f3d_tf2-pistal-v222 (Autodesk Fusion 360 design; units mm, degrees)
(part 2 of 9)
sketch "Sketch12" plane through (15, 0, 0) normal (-1, 0, 0) x axis (0, -1, 0)
  line L1 (-233.7172, -58) -> (-233.7172, -15.2961)
  line L2 (-211.3329, -58) -> (-233.7172, -58)
  line L3 (-182.3761, -29.6952) -> (-211.3329, -58)
  line L4 (-196.2783, -29.6952) -> (-182.3761, -29.6952)
  line L5 (-196.2783, -15.2961) -> (-196.2783, -29.6952)
  line L6 (-233.7172, -15.2961) -> (-196.2783, -15.2961)
  line L7 (-233.7172, -58) -> (-211.3329, -58)
  line L8 (-233.7172, -79.8803) -> (-233.7172, -58)
  line L9 (-211.3329, -58) -> (-233.7172, -79.8803)
  line L10 (-227, -25.812) -> (-233.7172, -25.812)
  line L11 (-221, -47) -> (-227, -25.812)
  line L12 (-216.582, -57.5943) -> (-223.3416, -55.7758)
  line L13 (-223.3416, -55.7758) -> (-242.8252, -128.2009)
  line L14 (-220.8968, -47.3272) -> (-223.3416, -55.7758)
  line L15 (-221, -47) -> (-220.8968, -47.3272)
  point P11 (-233.7172, -25.812)
  point P14 (-223.3416, -55.7758)
  point P17 (-223.3416, -55.7758)
  coincident L1 P11
  perpendicular L1 L10
  coincident P14 P17
extrude "Extrude8" new body sketch "Sketch12" profile of L1 L2 L7 L8 L9 L10 L11 L13 L14 L15 along normal blind 15
delete_face "DeleteFace5"
sketch "Sketch13" plane through (17.9981, 0, 0) normal (1, 0, 0) x axis (0, 1, 0)
  line L1 (149.9264, -64.082) -> (155.6873, -48.7302)
  line L2 (132.0175, -155.1313) -> (149.9264, -64.082)
  line L3 (171.9916, -32.8813) -> (200.2987, -133.9094)
  curve K1 (162.1012, -64.9669) -> (152.9897, -33.2509)
  line L4 (134.4899, -205.3434) -> (162.1012, -64.9669)
  line L5 (149.9264, -64.082) -> (132.0175, -155.1313)
  arc A1 centre (162.3398, -25.3102) radius 133.3153 clockwise from (186.1858, -156.4755) to (132.0175, -155.1313)
  arc A2 centre (182.9662, -138.7658) radius 18 clockwise from (200.2987, -133.9094) to (186.1858, -156.4755)
  arc A3 centre (162.3398, -25.3102) radius 12.267 clockwise from (152.9897, -33.2509) to (171.9916, -32.8813)
  arc A4 centre (141.1755, -43.2845) radius 15.5 clockwise from (152.9897, -33.2509) to (155.6873, -48.7302)
  point P10 (152.9897, -33.2509)
  point P12 (152.9897, -33.2509)
  coincident P10 P12
  parallel L4 L5
split "Split6"
split "Split7"
move "Move13"
combine "Combine6"
delete_face "DeleteFace6"
delete_face "DeleteFace7"
delete_face "DeleteFace8"
delete_face "DeleteFace9"
delete_face "DeleteFace10"
delete_face "DeleteFace11"
delete_face "DeleteFace12"
delete_face "DeleteFace13"
delete_face "DeleteFace14"
delete_face "DeleteFace15"
fillet "Fillet12" radius 1
fillet "Fillet13" radius 1
sketch "Sketch14" plane through (12.4927, 0, 0) normal (1, 0, 0) x axis (0, 1, 0)
  line L1 (199.7352, -62.1263) -> (223.3416, -55.7758)
  line L2 (199.7359, -62.129) -> (199.7352, -62.1263)
  line L3 (199.7459, -62.1263) -> (199.7359, -62.129)
  line L4 (219.2287, -134.5488) -> (199.7459, -62.1263)
  line L5 (242.8252, -128.2009) -> (219.2287, -134.5488)
  line L6 (223.3416, -55.7758) -> (242.8252, -128.2009)
  line L7 (233.7172, -79.8803) -> (211.3329, -58)
  line L8 (233.7172, -15.2961) -> (233.7172, -79.8803)
  curve K1 (274.1373, -137.1288) -> (233.7172, -54.0384)
  line L9 (250.6342, -126.1002) -> (242.8252, -128.2009)
  line L10 (255.2867, -143.3949) -> (250.6342, -126.1002)
  line L11 (274.1373, -137.1288) -> (255.2867, -143.3949)
  point P12 (233.7172, -54.0384)
  point P7 (242.8252, -128.2009)
  point P15 (242.8252, -128.2009)
  coincident L8 P12
  coincident P7 P15
  perpendicular L6 L9
  perpendicular L9 L10
extrude "Extrude9" new body sketch "Sketch14" profile of L6 L7 L8 K1 L9 L10 L11 along normal blind 7.505 and against normal blind 12.493
split "Split8"
split "Split9"
combine "Combine7"
move_face "MoveFace4"
extrude "Extrude10" cut of existing geometry blind -1
fillet "Fillet14" radius 10
sketch "Sketch15" plane through (-18.0019, 0, 0) normal (-1, 0, 0) x axis (0, -1, 0)
  curve K1 (-163.8476, -56.0881) -> (-163.931, -57.8793)
  curve K2 (-163.8476, -56.0881) -> (-150.2901, -27.6086)
  line L1 (-200.2987, -133.9094) -> (-171.9916, -32.8813)
  line L2 (-163.0153, -60.3193) -> (-143.9303, -157.3483)
  line L3 (-163.931, -57.8793) -> (-163.0153, -60.3193)
  curve K3 (-150.2901, -27.6086) -> (-148.0856, -25.9147)
  arc A1 centre (-162.3398, -25.3102) radius 12.267 clockwise from (-171.9916, -32.8813) to (-150.2901, -27.6086)
  arc A2 centre (-182.9662, -138.7658) radius 18 clockwise from (-186.1858, -156.4755) to (-200.2987, -133.9094)
  arc A3 centre (-162.3398, -25.3102) radius 133.3153 clockwise from (-143.9303, -157.3483) to (-186.1858, -156.4755)
  arc A4 centre (-162.3398, -25.3102) radius 14.267 clockwise from (-170.265, -13.447) to (-148.0856, -25.9147)
  circle C1 centre (-162.3398, -25.3102) radius 14.267
  point P12 (-148.0856, -25.9147)
  concentric A4 C1
  coincident P12 C1
extrude "Extrude11" new body sketch "Sketch15" profile of K2 C1 K3 against normal blind 5
combine "Combine8"
fillet "Fillet15" radius 2
sketch "Sketch16" plane through (17.9981, 0, 0) normal (1, 0, 0) x axis (0, 1, 0)
  curve K1 (163.8476, -56.0881) -> (163.931, -57.8793)
  line L1 (163.0153, -60.3193) -> (163.931, -57.8793)
  line L2 (143.9303, -157.3483) -> (163.0153, -60.3193)
  line L3 (171.9916, -32.8813) -> (200.2987, -133.9094)
  curve K2 (150.2901, -27.6086) -> (163.8476, -56.0881)
  curve K3 (148.0856, -25.9147) -> (150.2901, -27.6086)
  arc A1 centre (162.3398, -25.3102) radius 133.3153 clockwise from (186.1858, -156.4755) to (143.9303, -157.3483)
  arc A2 centre (182.9662, -138.7658) radius 18 clockwise from (200.2987, -133.9094) to (186.1858, -156.4755)
  arc A3 centre (162.3398, -25.3102) radius 12.267 clockwise from (150.2901, -27.6086) to (171.9916, -32.8813)
  arc A4 centre (162.3398, -25.3102) radius 14.267 clockwise from (148.0856, -25.9147) to (170.265, -13.447)
  circle C1 centre (162.3398, -25.3102) radius 14.267
  point P13 (148.0856, -25.9147)
  concentric A1 C1
  coincident P13 C1
extrude "Extrude12" new body sketch "Sketch16" profile of K2 C1 K3 against normal blind 5
combine "Combine9"
fillet "Fillet16" radius 2
combine "Combine10"
move_face "MoveFace5"
combine "Combine11"
move_face "MoveFace6"
move_face "MoveFace7"
move "Move1"
move_face "MoveFace1"
move "Move14" RotateAngle 30
sketch "Sketch17" plane through (0, 26.7264, -99.3486) normal (0, -0.2598, 0.9657) x axis (1, 0, 0)
  line L1 (5.4981, 153.3307) -> (-5.5019, 153.3307)
  line L2 (12.4981, 176.7509) -> (12.4981, 160.3307)
  line L3 (9.3981, 176.7509) -> (12.4981, 176.7509)
  line L4 (9.3981, 163.0135) -> (9.3981, 176.7509)
  line L5 (8.9981, 162.6135) -> (9.3981, 163.0135)
  line L6 (8.9981, 160.2587) -> (8.9981, 162.6135)
  line L7 (-4.5019, 155.7587) -> (4.4981, 155.7587)
  line L8 (-9.0019, 162.6135) -> (-9.0019, 160.2587)
  line L9 (-9.4019, 163.0135) -> (-9.0019, 162.6135)
  line L10 (-9.4019, 176.7509) -> (-9.4019, 163.0135)
  line L11 (-12.4949, 176.7509) -> (-9.4019, 176.7509)
  line L12 (-12.4949, 176.7407) -> (-12.4949, 176.7509)
  line L13 (-12.5019, 176.7407) -> (-12.4949, 176.7407)
  line L14 (-12.5019, 160.3307) -> (-12.5019, 176.7407)
  line L15 (-13.0019, 160.1268) -> (-13.0019, 159.1143)
  line L16 (12.9981, 159.1143) -> (12.9981, 160.1268)
  line L17 (12.9981, 160.1268) -> (-13.0019, 160.1268)
  arc A1 centre (-5.5019, 160.3307) radius 7 clockwise from (-5.5019, 153.3307) to (-12.5019, 160.3307)
  arc A2 centre (5.4981, 160.3307) radius 7 clockwise from (12.4981, 160.3307) to (5.4981, 153.3307)
  arc A3 centre (4.4981, 160.2587) radius 4.5 clockwise from (8.9981, 160.2587) to (4.4981, 155.7587)
  arc A4 centre (-4.5019, 160.2587) radius 4.5 clockwise from (-4.5019, 155.7587) to (-9.0019, 160.2587)
  arc A5 centre (-0.0019, 162.4117) radius 13.4117 clockwise from (12.9981, 159.1143) to (-13.0019, 159.1143)
  point P25 (-13.0019, 160.1268)
  point P28 (-13.0019, 160.1268)
  point P26 (12.9981, 160.1268)
  point P29 (12.9981, 160.1268)
  point P27 (12.9981, 159.1143)
  point P31 (12.9981, 159.1143)
  point P24 (-13.0019, 159.1143)
  point P30 (-13.0019, 159.1143)
  coincident P25 P28
  coincident P26 P29
  coincident P27 P31
  coincident P24 P30
split "Split10"
delete_face "DeleteFace16"
delete_face "DeleteFace17"
delete_face "DeleteFace18"
fillet "Fillet17" radius 1.5
sketch "Sketch18" plane through (12.4927, 0, 0) normal (1, 0, 0) x axis (0, 1, 0)
  line L1 (242.8252, -128.2009) -> (228.4379, -74.7198)
  line L2 (250.6342, -126.1002) -> (242.8252, -128.2009)
  line L3 (255.2867, -143.3949) -> (250.6342, -126.1002)
  line L4 (274.1373, -137.1288) -> (255.2867, -143.3949)
  curve K1 (261.4021, -106.9418) -> (274.1373, -137.1288)
  line L5 (228.4379, -74.7198) -> (261.4021, -106.9418)
  arc A1 centre (236.9306, -113.2524) radius 18 clockwise from (249.5127, -100.3804) to (248.5737, -126.9797)
  arc A2 centre (236.9306, -113.2524) radius 21.6199 clockwise from (252.2054, -97.9522) to (250.3613, -130.1945)
  point P13 (252.2054, -97.9522)
  point P10 (236.9306, -113.2524)
  point P11 (236.9306, -113.2524)
  coincident L5 P13
  coincident P10 P11
extrude "Extrude13" add sketch "Sketch18" profile of L3 L4 K1 L5 A2 along normal blind 7.505
delete_face "DeleteFace19"
move_face "MoveFace8"
sketch "Sketch19" plane through (19.9977, 0, 0) normal (1, 0, 0) x axis (0, 1, 0)
  curve K1 (274.1373, -137.1288) -> (234.5414, -55.1914)
  curve K2 (232.7172, -49.4332) -> (234.5414, -55.1914)
  line L1 (232.7172, -29.6952) -> (232.7172, -49.4332)
  line L2 (196.2783, -29.6952) -> (232.7172, -29.6952)
  line L3 (182.3761, -29.6952) -> (196.2783, -29.6952)
  line L4 (252.2054, -97.9522) -> (182.3761, -29.6952)
  line L5 (245.7812, -146.5546) -> (242.446, -134.1569)
  line L6 (274.1373, -137.1288) -> (245.7812, -146.5546)
  line L7 (250.9952, -129.672) -> (249.8674, -128.5049)
  line L8 (238.5226, -140.3558) -> (250.9952, -129.672)
  arc A1 centre (236.9306, -113.2524) radius 21.6199 clockwise from (252.2054, -97.9522) to (242.446, -134.1569)
  arc A2 centre (162.3398, -25.3102) radius 135.3153 clockwise from (249.8674, -128.5049) to (217.1145, -149.0436)
  point P13 (249.8674, -128.5049)
  point P15 (249.8674, -128.5049)
  point P16 (250.9952, -129.672)
  coincident P13 P15
  coincident A1 P16
  tangent A1 L8
extrude "Extrude14" cut sketch "Sketch19" profile of A1 L5 A2 L8 against normal blind 0.5
move_face "MoveFace9"
move_face "MoveFace10"
mirror "Mirror3" mirrorStitchTolerance 0.1
sketch "Sketch20" plane through (21.9981, 0, 0) normal (1, 0, 0) x axis (0, 1, 0)
  line L1 (232.7172, -15.2961) -> (232.7172, -29.6952)
  line L2 (144.3129, -15.2961) -> (232.7172, -15.2961)
  line L3 (144.3129, -29.6952) -> (144.3129, -15.2961)
  line L4 (232.7172, -29.6952) -> (144.3129, -29.6952)
  line L5 (237.721, -10) -> (210, -10)
  line L6 (237.721, -33.2426) -> (237.721, -10)
  line L7 (210, -33.2426) -> (237.721, -33.2426)
  line L8 (210, -10) -> (210, -33.2426)
  horizontal L5
  vertical L6
  horizontal L7
  vertical L8
extrude "Extrude15" new body sketch "Sketch20" profile of L1 L2 L4 L5 L6 L7 L8 against normal blind 2
mirror "Mirror4" mirrorStitchTolerance 0.1
combine "Combine12"
combine "Combine13"
sketch "Sketch21" plane through (0, 0, -25.812) normal (0, 0, 1) x axis (-1, 0, 0)
  line L1 (-15, -232.7172) -> (-15, -227)
  line L2 (0, -232.7172) -> (-15, -232.7172)
  line L3 (0, -227) -> (0, -232.7172)
  line L4 (-15, -227) -> (0, -227)
  line L5 (-8.7952, -248.3191) -> (-8.7952, -208.8666)
  line L6 (8.7048, -248.3191) -> (8.7048, -208.8666)
extrude "Extrude16" add sketch "Sketch21" profile of L1 L2 L4 L5 along normal blind 10.516
sketch "Sketch22" plane through (0, 0, -25.812) normal (0, 0, 1) x axis (-1, 0, 0)
  line L1 (15, -227) -> (15, -232.7172)
  line L2 (0, -227) -> (15, -227)
  line L3 (0, -232.7172) -> (0, -227)
  line L4 (15, -232.7172) -> (0, -232.7172)
  line L5 (8.7048, -248.3191) -> (8.7048, -208.8666)
extrude "Extrude17" add sketch "Sketch22" profile of L1 L2 L4 L5 along normal blind 10.516
move_face "MoveFace11"
move_face "MoveFace12"
extrude "Extrude18" add of existing geometry blind 0
extrude "Extrude19" add of existing geometry blind 0
fillet "Fillet18" radius 8
extrude "Extrude20" cut of existing geometry blind 0
move_face "MoveFace13"
fillet "Fillet19" radius 8
delete_face "DeleteFace20"
move_face "MoveFace14"
delete_face "DeleteFace21"
delete_face "DeleteFace22"
move_face "MoveFace15"
fillet "Fillet20" radius 10
fillet "Fillet21" radius 10
fillet "Fillet22" radius 1
mirror "Mirror5" mirrorStitchTolerance 0.1 bodies "Gear 2"
combine "Combine14"
sketch "Sketch23" plane through (19.9977, 0, 0) normal (1, 0, 0) x axis (0, 1, 0)
  line L1 (240.0468, -84.669) -> (183.8067, -29.6952)
  curve K1 (240.0468, -84.669) -> (225.9553, -60.3717)
  curve K2 (225.9553, -60.3717) -> (222.2172, -48.7291)
  line L2 (222.2172, -15.2961) -> (222.2172, -48.7291)
  line L3 (210, -15.2961) -> (222.2172, -15.2961)
  line L4 (210, -29.6952) -> (210, -15.2961)
  line L5 (196.2783, -29.6952) -> (210, -29.6952)
  line L6 (183.8067, -29.6952) -> (196.2783, -29.6952)
  line L7 (252.4034, -17.2714) -> (230.0662, -37.4329)
  line L8 (252.4034, -15.2961) -> (252.4034, -17.2714)
  line L9 (222.2172, -15.2961) -> (252.4034, -15.2961)
  line L10 (230.0662, -37.4329) -> (222.2172, -37.5779)
  line L11 (222.2172, -37.5779) -> (222.2172, -15.2961)
  point P6 (222.2172, -15.2961)
  point P13 (222.2172, -15.2961)
  point P14 (222.2172, -37.5779)
  point P15 (222.2172, -15.2961)
  perpendicular L3 L8
  coincident P6 P13
  perpendicular L2 L9
  coincident L2 P14
  coincident P6 P15
extrude "Extrude21" new body sketch "Sketch23" profile of L2 L7 L8 L9 L10 L11 against normal blind 39.995
fillet "Fillet23" radius 19.5
chamfer "Chamfer1" distance 10
chamfer "Chamfer2" distance 10
chamfer "Chamfer3" distance 7
split "Split11"
move_face "MoveFace16"
combine "Combine15"
split "Split12"
split "Split13"
combine "Combine16"
move_face "MoveFace1"
fillet "Fillet24" radius 2
sketch "Sketch24" plane through (-19.9977, 0, 0) normal (-1, 0, 0) x axis (0, -1, 0)
  line L1 (-196.2783, -29.6952) -> (-183.8067, -29.6952)
  line L2 (-210, -29.6952) -> (-196.2783, -29.6952)
  line L3 (-210, -15.2961) -> (-210, -29.6952)
  line L4 (-222.2172, -15.2961) -> (-210, -15.2961)
  line L5 (-222.2172, -48.7291) -> (-222.2172, -15.2961)
  curve K1 (-222.2172, -48.7291) -> (-225.9553, -60.3717)
  curve K2 (-225.9553, -60.3717) -> (-240.0468, -84.669)
  line L6 (-196.2783, -29.6952) -> (-210, -29.6952)
  line L7 (-144.3129, -29.6952) -> (-196.2783, -29.6952)
  line L8 (-264.6265, -140.2903) -> (-247.6, -145.9501)
  line L9 (-256.1132, -143.1202) -> (-210, -29.6952)
  curve K3 (-257.3894, -122.901) -> (-264.6265, -140.2903)
  line L10 (-247.6, -145.9501) -> (-264.6265, -140.2903)
  line L11 (-244.9647, -136.1543) -> (-247.6, -145.9501)
  line L12 (-244.9647, -136.1543) -> (-244.6769, -135.0842)
  line L13 (-250.9952, -129.672) -> (-244.6769, -135.0842)
  line L14 (-251.6458, -130.4315) -> (-250.9952, -129.672)
  line L15 (-182.3761, -29.6952) -> (-183.8067, -29.6952)
  line L16 (-239.3478, -85.3841) -> (-240.0468, -84.669)
  line L17 (-182.3761, -29.6952) -> (-239.3478, -85.3841)
  arc A1 centre (-236.9306, -113.2524) radius 22.6199 clockwise from (-251.6458, -130.4315) to (-257.3894, -122.901)
  point P10 (-210, -29.6952)
  point P16 (-210, -29.6952)
  point P17 (-256.1132, -143.1202)
  coincident P10 P16
  midpoint L8 P17
extrude "Extrude22" new body sketch "Sketch24" profile of L1 L2 L6 L7 L8 L9 L10 L11 L12 L13 L15 L17 against normal blind 1.996
mirror "Mirror6" mirrorStitchTolerance 0.1
combine "Combine17"
combine "Combine18"
chamfer "Chamfer4" distance 0.34
sketch "Sketch25" plane through (0, 0, -29.6952) normal (0, 0, 1) x axis (-1, 0, 0)
  line L1 (-18.0017, -196.2783) -> (-18.0017, -182.3761)
  line L2 (-15, -196.2783) -> (-18.0017, -196.2783)
  line L3 (-15, -182.3761) -> (-15, -196.2783)
  line L4 (-18.0017, -182.3761) -> (-15, -182.3761)
  line L5 (-20, -182.3761) -> (-18.0017, -182.3761)
  line L6 (-19.9981, -196.2783) -> (-18.0017, -196.2783)
  line L7 (-19.9981, -144.3129) -> (-19.9981, -196.2783)
  point P2 (-18.0017, -182.3761)
  point P6 (-18.0017, -182.3761)
  coincident P2 P6
  perpendicular L1 L5
extrude "Extrude23" new body sketch "Sketch25" along normal blind 2
mirror "Mirror7" mirrorStitchTolerance 0.1
combine "Combine19"
combine "Combine20"
move_face "MoveFace17"
split "Split14"
combine "Combine21"
combine "Combine22"
move_face "MoveFace18"
sketch "Sketch26" plane through (19.9977, 0, 0) normal (1, 0, 0) x axis (0, 1, 0)
  line L1 (227.5887, -72.0555) -> (210, -28.7924)
  curve K1 (227.5887, -72.0555) -> (227.8766, -72.7728)
  line L2 (240.0468, -84.669) -> (227.8766, -72.7728)
  curve K2 (240.0468, -84.669) -> (225.9553, -60.3717)
  curve K3 (225.9553, -60.3717) -> (222.2172, -48.7291)
  line L3 (222.2172, -18.0746) -> (222.2172, -48.7291)
  line L4 (225.4047, -18.0157) -> (222.2172, -18.0746)
  curve K4 (225.4047, -18.0157) -> (225.4041, -17.9302)
  line L5 (225.4041, -17.9302) -> (225.4039, -17.9036)
  curve K5 (225.4039, -17.9036) -> (225.4034, -17.7015)
  line L6 (225.4034, -0.2961) -> (225.4034, -17.7015)
  line L7 (210, -0.2961) -> (225.4034, -0.2961)
  line L8 (210, -28.7924) -> (210, -0.2961)
  line L9 (263.0459, -29.0909) -> (215, 35)
split "Split15"
remove_body "RemoveBody1"
remove_body "RemoveBody2"
sketch "Sketch27" plane through (0, 0, -0.2961) normal (0, 0, 1) x axis (-1, 0, 0)
  line L1 (-9.0952, -241.4598) -> (-16.2464, -241.4598)
  line L2 (-9.0952, -227) -> (-9.0952, -241.4598)
  line L3 (-15, -227) -> (-9.0952, -227)
  line L4 (-15, -196.2783) -> (-15, -227)
  line L5 (-19.9981, -196.2783) -> (-15, -196.2783)
  line L6 (-19.9981, -144.3129) -> (-19.9981, -196.2783)
  line L7 (-21.9981, -144.3129) -> (-19.9981, -144.3129)
  line L8 (-21.9981, -210) -> (-21.9981, -144.3129)
  line L9 (-19.9977, -210) -> (-21.9981, -210)
  line L10 (-19.9977, -225.4034) -> (-19.9977, -210)
  line L11 (-17.3189, -238.8705) -> (-19.9977, -225.4034)
  line L12 (-16.2464, -241.4598) -> (-17.3189, -238.8705)
  curve K1 (-21.9981, -210) -> (-19.9977, -222.2172)
  point P14 (-19.9977, -222.2172)
  point P15 (-19.9977, -222.2172)
  point P10 (-21.9981, -210)
  point P17 (-21.9981, -210)
  coincident P14 P15
  coincident P10 P17
extrude "Extrude24" new body sketch "Sketch27" profile of L9 L10 K1 against normal blind 29.399
move_face "MoveFace19"
move_face "MoveFace20"
move_face "MoveFace21"
delete_face "DeleteFace23"
move_face "MoveFace22"
delete_face "DeleteFace24"
sketch "Sketch28" plane through (0, 144.3129, 0) normal (0, -1, 0) x axis (1, 0, 0)
  line L1 (-18.3981, -0.2961) -> (-18.3981, -29.6952)
  line L2 (-19.9977, -0.2961) -> (-18.3981, -0.2961)
  line L3 (-19.9977, -29.6952) -> (-19.9977, -0.2961)
  line L4 (-18.3981, -29.6952) -> (-19.9977, -29.6952)
  line L5 (-12.7981, -21.7117) -> (-12.7981, -21.8255)
  line L6 (-12.7981, -21.9467) -> (-12.7981, -21.8116)
  line L7 (-12.7981, -21.9467) -> (-12.7981, -22.2857)
  line L8 (-12.7981, -22.2857) -> (-12.7981, -21.8768)
  line L9 (-12.7981, -21.8768) -> (-12.7981, -20.9044)
  line L10 (-12.7981, -20.8065) -> (-12.7981, -20.9044)
  line L11 (-12.7981, -20.2907) -> (-12.7981, -20.8065)
  line L12 (-12.7981, -20.2907) -> (-12.7981, -20.2008)
  line L13 (-12.7981, -19.9583) -> (-12.7981, -20.2008)
  line L14 (-12.7981, -20.0459) -> (-12.7981, -19.9798)
  line L15 (-12.7981, -20.0799) -> (-12.7981, -19.9159)
  line L16 (-12.7981, -19.9159) -> (-12.7981, -19.4286)
  line L17 (-12.7981, -19.4286) -> (-12.7981, -18.8037)
  line L18 (-12.7981, -18.7819) -> (-12.7981, -18.8037)
  line L19 (-12.7981, -18.3715) -> (-12.7981, -18.7819)
  line L20 (-12.7981, -18.3715) -> (-12.7981, -18.2733)
  line L21 (-12.7981, -17.879) -> (-12.7981, -18.2733)
  line L22 (-12.7981, -17.866) -> (-12.7981, -17.879)
  line L23 (-12.7981, -17.866) -> (-12.7981, -17.2868)
  line L24 (-12.7981, -17.2868) -> (-12.7981, -16.7952)
  line L25 (-12.7981, -16.7952) -> (-12.7981, -16.5906)
  line L26 (-12.7981, -16.6706) -> (-12.7981, -16.6129)
  line L27 (-12.7981, -16.4281) -> (-12.7981, -16.6868)
  line L28 (-12.7981, -16.4281) -> (-12.7981, -16.3366)
  line L29 (-12.7981, -15.8288) -> (-12.7981, -16.3366)
  line L30 (-12.7981, -15.7388) -> (-12.7981, -15.8288)
  line L31 (-12.7981, -15.7388) -> (-12.7981, -14.7985)
  line L32 (-12.7981, -14.7985) -> (-12.7981, -14.3775)
  line L33 (-12.7981, -14.3775) -> (-12.7981, -14.6657)
  line L34 (-12.7981, -14.794) -> (-12.7981, -14.6657)
  line L35 (-12.7981, -14.7563) -> (-12.7981, -14.8826)
  line L36 (-12.7981, -14.7563) -> (-12.7981, -14.6854)
  line L37 (-12.7981, -14.1416) -> (-12.7981, -14.6854)
  line L38 (-12.7981, -13.9882) -> (-12.7981, -14.1416)
  line L39 (-12.7981, -13.9882) -> (-12.7981, -12.8299)
  line L40 (-12.7981, -12.8299) -> (-12.7981, -12.5436)
  line L41 (-12.7981, -12.5436) -> (-12.7981, -13.2584)
  line L42 (-12.7981, -13.4378) -> (-12.7981, -13.2584)
  line L43 (-12.7981, -13.4378) -> (-12.7981, -13.6462)
  line L44 (-12.7981, -13.6107) -> (-12.7981, -13.5711)
  line L45 (-12.7981, -13.0741) -> (-12.7981, -13.5711)
  line L46 (-12.7981, -12.8806) -> (-12.7981, -13.0741)
  line L47 (-12.7981, -12.8806) -> (-12.7981, -11.6808)
  line L48 (-12.7981, -11.6808) -> (-12.7981, -11.5728)
  line L49 (-12.7981, -11.5728) -> (-12.7981, -12.6052)
  line L50 (-12.7981, -12.8085) -> (-12.7981, -12.6052)
  line L51 (-12.7981, -12.8085) -> (-12.7981, -13.1658)
  line L52 (-12.7981, -13.1656) -> (-12.7981, -13.1635)
  line L53 (-12.7981, -12.7888) -> (-12.7981, -13.1635)
  line L54 (-12.7981, -12.5848) -> (-12.7981, -12.7888)
  line L55 (-12.7981, -12.5848) -> (-12.7981, -11.526)
  line L56 (-12.7981, -11.6127) -> (-12.7981, -11.526)
  line L57 (-12.7981, -11.6127) -> (-12.7981, -12.8057)
  line L58 (-12.7981, -13.0019) -> (-12.7981, -12.8057)
  line L59 (-12.7981, -13.0019) -> (-12.7981, -13.4888)
  line L60 (-12.7981, -13.5244) -> (-12.7981, -13.4888)
  line L61 (-12.7981, -13.3292) -> (-12.7981, -13.553)
  line L62 (-12.7981, -13.1457) -> (-12.7981, -13.3292)
  line L63 (-12.7981, -13.1457) -> (-12.7981, -12.3892)
  line L64 (-12.7981, -12.6574) -> (-12.7981, -12.3892)
  line L65 (-12.7981, -12.6574) -> (-12.7981, -13.8293)
  line L66 (-12.7981, -13.9885) -> (-12.7981, -13.8293)
  line L67 (-12.7981, -13.9885) -> (-12.7981, -14.5311)
  line L68 (-12.7981, -14.5991) -> (-12.7981, -14.5311)
  line L69 (-12.7981, -14.5991) -> (-12.7981, -14.7128)
  line L70 (-12.7981, -14.4779) -> (-12.7981, -14.613)
  line L71 (-12.7981, -14.4779) -> (-12.7981, -14.1388)
  line L72 (-12.7981, -14.5477) -> (-12.7981, -14.1388)
  line L73 (-12.7981, -14.5477) -> (-12.7981, -15.5202)
  line L74 (-12.7981, -15.6181) -> (-12.7981, -15.5202)
  line L75 (-12.7981, -15.6181) -> (-12.7981, -16.1339)
  line L76 (-12.7981, -16.2238) -> (-12.7981, -16.1339)
  line L77 (-12.7981, -16.2238) -> (-12.7981, -16.4663)
  line L78 (-12.7981, -16.3786) -> (-12.7981, -16.4448)
  line L79 (-12.7981, -16.3447) -> (-12.7981, -16.5087)
  line L80 (-12.7981, -16.996) -> (-12.7981, -16.5087)
  line L81 (-12.7981, -16.996) -> (-12.7981, -17.6209)
  line L82 (-12.7981, -17.6427) -> (-12.7981, -17.6209)
  line L83 (-12.7981, -17.6427) -> (-12.7981, -18.053)
  line L84 (-12.7981, -18.1513) -> (-12.7981, -18.053)
  line L85 (-12.7981, -18.1513) -> (-12.7981, -18.5456)
  line L86 (-12.7981, -18.5586) -> (-12.7981, -18.5456)
  line L87 (-12.7981, -18.5586) -> (-12.7981, -19.1378)
  line L88 (-12.7981, -19.6294) -> (-12.7981, -19.1378)
  line L89 (-12.7981, -19.6294) -> (-12.7981, -19.8339)
  line L90 (-12.7981, -19.754) -> (-12.7981, -19.8116)
  line L91 (-12.7981, -19.7378) -> (-12.7981, -19.9964)
  line L92 (-12.7981, -20.088) -> (-12.7981, -19.9964)
  line L93 (-12.7981, -20.088) -> (-12.7981, -20.5957)
  line L94 (-12.7981, -20.6858) -> (-12.7981, -20.5957)
  line L95 (-12.7981, -20.6858) -> (-12.7981, -21.6261)
  line L96 (-12.7981, -22.0471) -> (-12.7981, -21.6261)
  line L97 (-12.7981, -22.0471) -> (-12.7981, -21.7589)
  line L98 (-12.7981, -21.6306) -> (-12.7981, -21.7589)
  line L99 (-12.7981, -21.542) -> (-12.7981, -21.6682)
  line L100 (-12.7981, -21.7392) -> (-12.7981, -21.6682)
  line L101 (-12.7981, -21.7392) -> (-12.7981, -22.283)
  line L102 (-12.7981, -22.4364) -> (-12.7981, -22.283)
  line L103 (-12.7981, -22.4364) -> (-12.7981, -23.5946)
  line L104 (-12.7981, -23.8809) -> (-12.7981, -23.5946)
  line L105 (-12.7981, -23.8809) -> (-12.7981, -23.1662)
  line L106 (-12.7981, -22.9868) -> (-12.7981, -23.1662)
  line L107 (-12.7981, -22.7784) -> (-12.7981, -22.9868)
  line L108 (-12.7981, -22.8534) -> (-12.7981, -22.8139)
  line L109 (-12.7981, -22.8534) -> (-12.7981, -23.3505)
  line L110 (-12.7981, -23.5439) -> (-12.7981, -23.3505)
  line L111 (-12.7981, -23.5439) -> (-12.7981, -24.7438)
  line L112 (-12.7981, -24.8518) -> (-12.7981, -24.7438)
  line L113 (-12.7981, -24.8518) -> (-12.7981, -23.8193)
  line L114 (-12.7981, -23.6161) -> (-12.7981, -23.8193)
  line L115 (-12.7981, -23.2588) -> (-12.7981, -23.6161)
  line L116 (-12.7981, -23.2611) -> (-12.7981, -23.259)
  line L117 (-12.7981, -23.2611) -> (-12.7981, -23.6358)
  line L118 (-12.7981, -23.8398) -> (-12.7981, -23.6358)
  line L119 (-12.7981, -23.8398) -> (-12.7981, -24.8985)
  line L120 (-12.7981, -24.8985) -> (-12.7981, -24.8119)
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  point P4 (-19.9977, -0.2961)
  point P266 (-19.9977, -0.2961)
  coincident P4 P266
extrude "Extrude25" new body sketch "Sketch28" against normal blind 82.687
mirror "Mirror8" mirrorStitchTolerance 0.1
move_face "MoveFace23"
remove_body "RemoveBody3"
move_face "MoveFace24"
combine "Combine23"
combine "Combine24"
delete_face "DeleteFace25"
delete_face "DeleteFace26"
delete_face "DeleteFace27"
delete_face "DeleteFace28"
delete_face "DeleteFace29"
sketch "Sketch29" plane through (-18.0017, 0, 0) normal (-1, 0, 0) x axis (0, -1, 0)
  line L1 (-210, -29.6952) -> (-182.3761, -29.6952)
  line L2 (-228.0891, -74.1891) -> (-210, -29.6952)
  line L3 (-228.4603, -74.7417) -> (-228.0891, -74.1891)
  line L4 (-182.3761, -29.6952) -> (-228.4603, -74.7417)
  line L5 (-136.4052, -29.6952) -> (-182.3761, -29.6952)
  line L6 (-159.3888, -79.2671) -> (-148.3921, -52.2184)
  curve K1 (-222.2696, -154.3701) -> (-159.3888, -79.2671)
  curve K2 (-196.4, -86.9675) -> (-183.6, -73.0325)
  curve K3 (-173.6342, -72.8171) -> (-145.1434, -85.7171)
  line L7 (-264.6265, -140.2903) -> (-256.4365, -143.0127)
  line L8 (-146.3684, -179.6005) -> (-256.4365, -143.0127)
  line L9 (-228.4603, -74.7417) -> (-256.4365, -143.0127)
  arc A1 centre (-116.7403, -54.6121) radius 31.7422 clockwise from (-137.1663, -78.9091) to (-136.4052, -29.6952)
  point P2 (-182.3761, -29.6952)
  point P6 (-182.3761, -29.6952)
  point P10 (-148.3921, -52.2184)
  point P12 (-190, -80)
  point P11 (-159.3888, -79.2671)
  point P18 (-256.4365, -143.0127)
  point P20 (-256.4365, -143.0127)
  point P13 (-222.2696, -154.3701)
  point P22 (-256.4365, -143.0127)
  point P5 (-228.4603, -74.7417)
  point P23 (-228.4603, -74.7417)
  coincident P2 P6
  parallel L1 L5
  coincident A1 P10
  parallel L2 L6
  midpoint P12 K2
  midpoint P11 K3
  coincident P18 P20
  parallel L7 L8
  coincident P13 L8
  coincident P18 P22
  coincident P5 P23
extrude "Extrude26" new body sketch "Sketch29" profile of L1 L2 L3 L4 L5 A1 L6 K1 L8 L9 along normal blind 1.996
move_face "MoveFace25"
sketch "Sketch30" plane through (-18.3981, 0, 0) normal (1, 0, 0) x axis (0, 1, 0)
  line L1 (136.4052, -29.6952) -> (210, -29.6952)
  line L2 (159.3888, -79.2671) -> (148.3921, -52.2184)
  curve K1 (222.2696, -154.3701) -> (159.3888, -79.2671)
  line L3 (256.4365, -143.0127) -> (222.2696, -154.3701)
  line L4 (228.4603, -74.7417) -> (256.4365, -143.0127)
  line L5 (228.0891, -74.1891) -> (228.4603, -74.7417)
  line L6 (210, -29.6952) -> (228.0891, -74.1891)
  line L7 (144.3129, -29.6952) -> (144.3129, -0.2961)
  line L8 (164.5241, -77.0908) -> (144.3129, -29.6952)
  arc A1 centre (116.7403, -54.6121) radius 31.7422 clockwise from (136.4052, -29.6952) to (148.3921, -52.2184)
  point P12 (144.3129, -29.6952)
  point P13 (144.3129, -29.6952)
  point P14 (164.5241, -77.0908)
  coincident P12 P13
  coincident K1 P14
extrude "Extrude27" new body sketch "Sketch30" profile of L1 A1 L2 K1 L8 along normal blind 18.398
combine "Combine25"
fillet "Fillet25" radius 5
sketch "Sketch31" plane through (-19.9977, 0, 0) normal (-1, 0, 0) x axis (0, -1, 0)
  line L1 (-210, -29.6952) -> (-143.7427, -29.6952)
  line L2 (-228.0891, -74.1891) -> (-210, -29.6952)
  line L3 (-228.4603, -74.7417) -> (-228.0891, -74.1891)
  line L4 (-256.4365, -143.0127) -> (-228.4603, -74.7417)
  line L5 (-222.2696, -154.3701) -> (-256.4365, -143.0127)
  curve K1 (-163.9876, -77.3028) -> (-222.2696, -154.3701)
  line L6 (-153.3078, -51.0336) -> (-163.9876, -77.3028)
  line L7 (-224.9066, -153.4936) -> (-194.6979, -62.6157)
  line L8 (-224.9066, -157.132) -> (-224.9066, -153.4936)
  line L9 (-193.862, -167.4515) -> (-224.9066, -157.132)
  line L10 (-144.6344, -71.4108) -> (-193.862, -167.4515)
  arc A1 centre (-116.7403, -54.6121) radius 36.7422 clockwise from (-153.3078, -51.0336) to (-143.7427, -29.6952)
  arc A2 centre (-162.3398, -25.3102) radius 12.267 clockwise from (-174.484, -27.041) to (-161.9033, -37.5694)
  circle C1 centre (-162.3398, -25.3102) radius 49.3837
  point P11 (-168.4385, -74.3159)
  point P16 (-194.6979, -62.6157)
  point P17 (-224.9066, -153.4936)
  point P20 (-144.6344, -71.4108)
  concentric A2 C1
  coincident P11 C1
  coincident C1 P16
  coincident L5 P17
  perpendicular L5 L7
  vertical L8
  perpendicular L7 L9
  coincident C1 P20
extrude "Extrude28" cut sketch "Sketch31" profile of L5 K1 L6 C1 L7 L8 L9 L10 against normal blind 1.6
move_face "MoveFace26" TranslateX 6 TranslateY 0 TranslateZ 0
move_face "MoveFace27" TranslateX 16 TranslateY 0 TranslateZ 0
move_face "MoveFace28" TranslateX 0 TranslateY 0 TranslateZ 9
move_face "MoveFace29" TranslateX 0 TranslateY -10 TranslateZ 0
fillet "Fillet26" radius 30
fillet "Fillet27" radius 1
fillet "Fillet28" radius 0.5
move "Move15" RotateAngle -30
sketch "Sketch32" plane through (-19.9977, 0, 0) normal (-1, 0, 0) x axis (0, -1, 0)
  line L1 (-153.3078, -51.0336) -> (-159.0188, -65.081)
  line L2 (-210, -29.6952) -> (-143.7427, -29.6952)
  line L3 (-228.0891, -74.1891) -> (-210, -29.6952)
  line L4 (-228.4603, -74.7417) -> (-228.0891, -74.1891)
  line L5 (-256.4365, -143.0127) -> (-228.4603, -74.7417)
  line L6 (-216.3761, -156.3292) -> (-256.4365, -143.0127)
  line L7 (-193.0159, -86.0541) -> (-216.3761, -156.3292)
  curve K1 (-140, -70) -> (-148.3921, -52.2184)
  line L8 (-140, -70) -> (-159.0188, -65.081)
  line L9 (-153.3078, -51.0336) -> (-148.3921, -52.2184)
  arc A1 centre (-162.3398, -16.3102) radius 48.8837 clockwise from (-159.0188, -65.081) to (-163.4071, -65.1822)
  arc A2 centre (-116.7403, -54.6121) radius 36.7422 clockwise from (-153.3078, -51.0336) to (-143.7427, -29.6952)
  arc A3 centre (-164.0731, -95.675) radius 30.5 clockwise from (-193.0159, -86.0541) to (-163.4071, -65.1822)
  arc A4 centre (-116.7403, -54.6121) radius 31.7422 clockwise from (-148.3921, -52.2184) to (-136.4052, -29.6952)
  point P16 (-148.3921, -52.2184)
  point P18 (-148.3921, -52.2184)
  point P3 (-159.0188, -65.081)
  point P21 (-159.0188, -65.081)
  point P22 (-148.3921, -52.2184)
  point P5 (-153.3078, -51.0336)
  point P23 (-153.3078, -51.0336)
  coincident P16 P18
  coincident P3 P21
  coincident P16 P22
  coincident P5 P23
extrude "Extrude29" new body sketch "Sketch32" profile of L1 K1 L8 L9 against normal blind 19.998
fillet "Fillet29" radius 5
fillet "Fillet30" radius 1
combine "Combine26"
move_face "MoveFace30" TranslateX 0 TranslateY -8 TranslateZ 0
delete_face "DeleteFace30"
fillet "Fillet31" radius 0.5
chamfer "Chamfer5" distance 0.45
chamfer "Chamfer6" distance 0.45
remove_body "RemoveBody4"
mirror "Mirror9" mirrorStitchTolerance 0.1
sketch "Sketch33" plane through (19.9977, 0, 0) normal (1, 0, 0) x axis (0, 1, 0)
  curve K1 (209.4603, -30.1452) -> (209.6429, -30.1443)
  line L1 (144.1511, -30.1452) -> (209.4603, -30.1452)
  line L2 (153.3896, -51.2349) -> (153.3078, -51.0336)
  curve K2 (150.1881, -66.332) -> (153.3896, -51.2349)
  line L3 (158.6388, -64.1463) -> (150.1881, -66.332)
  line L4 (159.119, -65.3274) -> (158.6388, -64.1463)
  line L5 (209.1721, -158.7239) -> (185.0159, -86.0541)
  line L6 (255.6377, -143.2782) -> (209.1721, -158.7239)
  line L7 (209.6429, -30.1443) -> (255.6377, -143.2782)
  curve K3 (148.3921, -52.2184) -> (143.2922, -67.2348)
  curve K4 (143.2922, -67.2348) -> (136.7565, -29.9764)
  line L8 (139.3878, -83.7751) -> (143.2922, -67.2348)
  curve K5 (75, -25) -> (139.3878, -83.7751)
  curve K6 (96.3894, -75) -> (114.049, -87.4869)
  line L9 (121.2561, -25) -> (75, -25)
  curve K7 (142, -30) -> (121.2561, -25)
  line L10 (143.7427, -29.6952) -> (136.8552, -29.6952)
  line L11 (136.1286, -29.6952) -> (141.5245, -29.6952)
  arc A1 centre (116.7403, -54.6121) radius 36.7422 clockwise from (144.1511, -30.1452) to (153.3078, -51.0336)
  arc A2 centre (156.0731, -95.675) radius 30.5 clockwise from (159.119, -65.3274) to (185.0159, -86.0541)
  arc A3 centre (116.7403, -54.6121) radius 31.7422 clockwise from (136.7565, -29.9764) to (148.3921, -52.2184)
  point P16 (136.7565, -29.9764)
  point P19 (136.7565, -29.9764)
  point P18 (143.2922, -67.2348)
  point P26 (143.2922, -67.2348)
  point P30 (105.2192, -81.2434)
  point P42 (141.5245, -29.6952)
  point P43 (136.1286, -29.6952)
  coincident P16 P19
  coincident P18 P26
  midpoint P30 K6
  horizontal L9
  coincident K7 P42
  coincident L10 P42
  coincident K4 P43
  parallel L10 L11
extrude "Extrude30" new body sketch "Sketch33" profile of K4 L8 K5 L9 K7 L10 L11 against normal blind 19.998 and against normal blind 10
fillet "Fillet32" radius 0.25
sketch "Sketch34" plane through (9.9977, 0, 0) normal (1, 0, 0) x axis (0, 1, 0)
  curve K1 (142.9765, -68.572) -> (142.5291, -68.3702)
  curve K2 (142.5291, -68.3702) -> (136.1286, -29.6952)
  line L1 (141.5245, -29.6952) -> (136.1286, -29.6952)
  curve K3 (141.5245, -29.6952) -> (121.2561, -25)
  line L2 (75, -25) -> (121.2561, -25)
  curve K4 (75, -25) -> (139.3878, -83.7751)
  line L3 (142.9765, -68.572) -> (139.3878, -83.7751)
  line L4 (136.7565, -29.9764) -> (136.8552, -29.6952)
  line L5 (136.8552, -29.6952) -> (136.7565, -29.9764)
  line L6 (136.1286, -29.6952) -> (141.5245, -29.6952)
  curve K5 (142.5291, -68.3702) -> (136.1286, -29.6952)
  curve K6 (136.7565, -29.9764) -> (136.1286, -29.6952)
  point P4 (136.1286, -29.6952)
  point P14 (136.1286, -29.6952)
  point P10 (136.7565, -29.9764)
  point P16 (136.7565, -29.9764)
  coincident P4 P14
  coincident P10 P16
extrude "Extrude31" new body sketch "Sketch34" profile of L1 L4 L5 L6 K6 against normal blind 9.998
combine "Combine27"
fillet "Fillet33" radius 5
fillet "Fillet34" radius 2
fillet "Fillet35" radius 2
mirror "Mirror10" mirrorStitchTolerance 0.1
sketch "Sketch35" plane through (-19.9977, 0, 0) normal (-1, 0, 0) x axis (0, -1, 0)
  line L1 (-251.4481, -130.7426) -> (-256.4365, -143.0127)
  curve K1 (-251.4481, -130.7426) -> (-251.4053, -130.6375)
  line L2 (-251.6458, -130.4315) -> (-251.4053, -130.6375)
  curve K2 (-257.3894, -122.901) -> (-264.6265, -140.2903)
  line L3 (-256.4365, -143.0127) -> (-264.6265, -140.2903)
  line L4 (-264.6265, -140.2903) -> (-256.4365, -143.0127)
  line L5 (-256.4365, -143.0127) -> (-274.1373, -137.1288)
  line L6 (-209.1721, -158.7239) -> (-256.4365, -143.0127)
  curve K3 (-267.0659, -151.2078) -> (-274.1373, -137.1288)
  line L7 (-181.0975, -174.5688) -> (-267.0659, -151.2078)
  line L8 (-179, -171) -> (-181.0975, -174.5688)
  line L9 (-176.7957, -162.8883) -> (-179, -171)
  line L10 (-207.2316, -152.8863) -> (-176.7957, -162.8883)
  line L11 (-209.1721, -158.7239) -> (-207.2316, -152.8863)
  arc A1 centre (-236.9306, -113.2524) radius 22.6199 clockwise from (-251.6458, -130.4315) to (-257.3894, -122.901)
  point P11 (-274.1373, -137.1288)
  point P12 (-274.1373, -137.1288)
  point P9 (-256.4365, -143.0127)
  point P13 (-256.4365, -143.0127)
  point P14 (-209.1721, -158.7239)
  point P15 (-209.1721, -158.7239)
  coincident P11 P12
  coincident P9 P13
  coincident P14 P15
  perpendicular L7 L9
extrude "Extrude32" new body sketch "Sketch35" profile of L3 L4 L5 L6 K3 L7 L8 L9 L10 L11 against normal blind 39.995
fillet "Fillet36" radius 10
fillet "Fillet37" radius 15.5
combine "Combine28"
move "Move2" TranslateX 0 TranslateY 0 TranslateZ -3
combine "Combine29"
delete_face "DeleteFace31"
move "Move3" TranslateX 0 TranslateY 0 TranslateZ 3
delete_face "DeleteFace32"
delete_face "DeleteFace33"
move_face "MoveFace31" TranslateX 0 TranslateY 0 TranslateZ 16
move "Move4" TranslateX 0 TranslateY 0 TranslateZ -35
move "Move5"
fillet "Fillet38" radius 7.5
combine "Combine30"
delete_face "DeleteFace34"
delete_face "DeleteFace35"
sketch "Sketch36" plane through (19.9973, 0, 0) normal (1, 0, 0) x axis (0, 1, 0)
  line L1 (206.7566, -153.0424) -> (208.6976, -158.8816)
  line L2 (191.5411, -158.0426) -> (206.7566, -153.0424)
  line L3 (193.0382, -163.5521) -> (191.5411, -158.0426)
  line L4 (255.6789, -146.5301) -> (193.0382, -163.5521)
  curve K1 (255.6789, -146.5301) -> (263.9987, -140.499)
  line L5 (256.4365, -143.0127) -> (263.9987, -140.499)
  line L6 (208.6976, -158.8816) -> (256.4365, -143.0127)
  line L7 (191.5411, -158.0426) -> (206.7566, -153.0424)
  line L8 (200.2258, -133.3957) -> (206.7566, -153.0424)
  curve K2 (191.5411, -158.0426) -> (200.2258, -133.3957)
  point P3 (206.7566, -153.0424)
  point P11 (206.7566, -153.0424)
  point P10 (191.5411, -158.0426)
  point P14 (191.5411, -158.0426)
  coincident P3 P11
  coincident P10 P14
extrude "Extrude33" new body sketch "Sketch36" profile of L2 L7 L8 K2 against normal blind 1.5
fillet "Fillet39" radius 0.2
fillet "Fillet40" radius 0.5
fillet "Fillet41" radius 0.5
mirror "Mirror11" mirrorStitchTolerance 0.1
fillet "Fillet42" radius 0.5
combine "Combine31"
fillet "Fillet43" radius 0.496
sketch "Sketch37" plane through (-19.9977, 0, 0) normal (-1, 0, 0) x axis (0, -1, 0)
  curve K1 (-209.4603, -30.1452) -> (-209.6429, -30.1443)
  line L1 (-255.6377, -143.2782) -> (-209.6429, -30.1443)
  line L2 (-209.1721, -158.7239) -> (-255.6377, -143.2782)
  line L3 (-185.0159, -86.0541) -> (-209.1721, -158.7239)
  line L4 (-158.6388, -64.1463) -> (-159.119, -65.3274)
  line L5 (-150.1881, -66.332) -> (-158.6388, -64.1463)
  curve K2 (-150.1881, -66.332) -> (-153.3896, -51.2349)
  line L6 (-153.3078, -51.0336) -> (-153.3896, -51.2349)
  line L7 (-209.4603, -30.1452) -> (-144.1511, -30.1452)
  line L8 (-150, -15.0034) -> (-226.0187, -15.0034)
  line L9 (-188.0094, -144.0551) -> (-150, -15.0034)
  line L10 (-188.0094, -155) -> (-188.0094, -144.0551)
  line L11 (-190.4367, -163.2414) -> (-188.0094, -155)
  line L12 (-262.7172, -139.2147) -> (-190.4367, -163.2414)
  line L13 (-222.3838, -55.843) -> (-257.0453, -141.1001)
  line L14 (-222.3838, -15.0034) -> (-222.3838, -55.843)
  arc A1 centre (-156.0731, -95.675) radius 30.5 clockwise from (-185.0159, -86.0541) to (-159.119, -65.3274)
  arc A2 centre (-116.7403, -54.6121) radius 36.7422 clockwise from (-153.3078, -51.0336) to (-144.1511, -30.1452)
  point P21 (-257.0453, -141.1001)
  point P23 (-222.3838, -15.0034)
  horizontal L8
  perpendicular L8 L10
  parallel L9 L11
  perpendicular L3 L12
  coincident L12 P21
  parallel L1 L13
  coincident L8 P23
  perpendicular L8 L14
extrude "Extrude34" new body sketch "Sketch37" profile of K1 L1 L3 A1 L7 L8 L9 L10 L11 L12 L13 L14 along normal blind 10
move_face "MoveFace33"
fillet "Fillet44" radius 7.5
fillet "Fillet45" radius 5
move_face "MoveFace34"
sketch "Sketch38" plane through (-21.9977, 0, 0) normal (-1, 0, 0) x axis (0, -1, 0)
  line L1 (-195.348, -161.6089) -> (-251.9805, -142.7837)
  line L2 (-188.0094, -155) -> (-188.9745, -158.2768)
  line L3 (-188.0094, -144.0551) -> (-188.0094, -155)
  line L4 (-152.8331, -24.6224) -> (-188.0094, -144.0551)
  line L5 (-214.8838, -15.0034) -> (-160.0275, -15.0034)
  line L6 (-222.3838, -55.843) -> (-222.3838, -22.5034)
  line L7 (-255.0352, -136.1558) -> (-222.3838, -55.843)
  arc A1 centre (-250.4033, -138.0389) radius 5 clockwise from (-251.9805, -142.7837) to (-255.0352, -136.1558)
  arc A2 centre (-193.7708, -156.8641) radius 5 clockwise from (-188.9745, -158.2768) to (-195.348, -161.6089)
  arc A3 centre (-160.0275, -22.5034) radius 7.5 clockwise from (-160.0275, -15.0034) to (-152.8331, -24.6224)
  arc A4 centre (-214.8838, -22.5034) radius 7.5 clockwise from (-222.3838, -22.5034) to (-214.8838, -15.0034)
  circle C1 centre (-212.9636, -95.9994) radius 16.2716
extrude "Extrude35" cut sketch "Sketch38" profile of C1 against normal blind 1
chamfer "Chamfer7" distance 1
chamfer "Chamfer8" distance 1.4
fillet "Fillet46" radius 1.5
mirror "Mirror12" mirrorStitchTolerance 0.1 bodies "Grip plate_L"
sketch "Sketch39" plane through (0, 25.7478, -99.5503) normal (0, 0.2504, -0.9681) x axis (-1, 0, 0)
  line L1 (-18.3981, 136.9465) -> (-18.3981, 139.0249)
  curve K1 (-18.3981, 136.9465) -> (-18.8981, 135.2582)
  line L2 (-18.9349, 135.2582) -> (-18.8981, 135.2582)
  curve K2 (-18.9349, 135.2582) -> (-18.9977, 135.2681)
  line L3 (-18.9977, 128.7938) -> (-18.9977, 135.2681)
  curve K3 (-14.9977, 122.4138) -> (-18.9977, 128.7938)
  line L4 (0.0003, 122.4138) -> (-14.9977, 122.4138)
  line L5 (0.0003, 137.6564) -> (0.0003, 122.4138)
  line L6 (-0.0001, 137.6564) -> (0.0003, 137.6564)
  line L7 (-0.0001, 138.0135) -> (-0.0001, 137.6564)
  line L8 (-17.3981, 138.0135) -> (-0.0001, 138.0135)
  curve K4 (-18.9977, 132.031) -> (-11.5276, 122.4138)
  line L9 (-20.4642, 135.4497) -> (-18.9977, 132.031)
  line L10 (-21, 118) -> (-20.4642, 135.4497)
  line L11 (-9.9977, 116.3649) -> (-21, 118)
  line L12 (-9.9649, 121.6438) -> (-11.5276, 122.4138)
  line L13 (-9.9977, 116.3649) -> (-9.9649, 121.6438)
  closed curve K5 centre (-17.3981, 139.0249)
  point P16 (-11.5276, 122.4138)
  point P18 (-18.9977, 132.031)
  point P15 (-9.9977, 116.3649)
  point P21 (-9.9977, 116.3649)
  point P23 (-9.9977, 116.3649)
  coincident L4 P16
  midpoint L3 P18
  coincident P15 P21
  coincident P15 P23
extrude "Extrude36" new body sketch "Sketch39" profile of L3 K3 L4 K4 L9 L10 L11 L12 L13 against normal blind 8
move_face "MoveFace35"
mirror "Mirror13" mirrorStitchTolerance 0.1
move_face "MoveFace36"
combine "Combine32"
combine "Combine33"
fillet "Fillet47" radius 0.98
sketch "Sketch40" plane through (19.9977, 0, 0) normal (1, 0, 0) x axis (0, 1, 0)
  line L1 (210.1841, -29.2452) -> (144.3129, -29.2452)
  line L2 (227.5887, -72.0555) -> (210.1841, -29.2452)
  curve K1 (227.8766, -72.7728) -> (227.5887, -72.0555)
  line L3 (240.0468, -84.669) -> (227.8766, -72.7728)
  curve K2 (225.9553, -60.3717) -> (240.0468, -84.669)
  curve K3 (222.2172, -48.7291) -> (225.9553, -60.3717)
  line L4 (222.2172, -0.2961) -> (222.2172, -48.7291)
  line L5 (144.3129, -0.2961) -> (222.2172, -0.2961)
  line L6 (144.3129, -29.2452) -> (144.3129, -0.2961)
  line L7 (121.2561, -25) -> (82.4575, -25)
  line L8 (75, -25) -> (82.4575, -25)
  curve K4 (141.5245, -29.6952) -> (121.2561, -25)
  line L9 (143.7427, -29.6952) -> (136.8552, -29.6952)
  line L10 (144.3129, -29.2452) -> (144.3129, -0.2961)
  line L11 (144.3129, -29.2452) -> (144.3129, -29.6952)
  line L12 (144.1511, -29.6952) -> (143.7427, -29.6952)
  line L13 (209.4603, -29.6952) -> (144.1511, -29.6952)
  curve K5 (19.0955, -3.324) -> (75, -25)
  line L14 (19.0955, -0.2961) -> (19.0955, -3.324)
  line L15 (19.0955, 10) -> (19.0955, -0.2961)
  line L16 (150, 10) -> (19.0955, 10)
  line L17 (144.3129, 10) -> (144.3129, -0.2961)
  point P14 (75, -25)
  point P24 (75, -25)
  point P19 (144.3129, -0.2961)
  point P29 (144.3129, -0.2961)
  point P33 (144.3129, 10)
  coincident P14 P24
  coincident P19 P29
  perpendicular L14 L16
  coincident L16 P33
  perpendicular L16 L17
extrude "Extrude37" new body sketch "Sketch40" profile of L6 L7 L8 K4 L9 L10 L11 L12 L13 K5 L14 L15 L16 L17 against normal blind 39.995
sketch "Sketch41" plane through (-19.9973, 0, 0) normal (-1, 0, 0) x axis (0, -1, 0)
  line L1 (-82.4575, -25) -> (-121.2561, -25)
  line L2 (-75, -25) -> (-82.4575, -25)
  curve K1 (-19.0955, -3.324) -> (-75, -25)
  line L3 (-19.0955, 10) -> (-19.0955, -3.324)
  line L4 (-144.3129, 10) -> (-19.0955, 10)
  line L5 (-144.3129, -29.6952) -> (-144.3129, 10)
  line L6 (-141.5245, -29.6952) -> (-144.3129, -29.6952)
  curve K2 (-121.2561, -25) -> (-141.5245, -29.6952)
  curve K3 (-121.2561, -25) -> (-141.5245, -29.6952)
  line L7 (-82.4575, -25) -> (-121.2561, -25)
  line L8 (-143.7427, -29.6952) -> (-136.8552, -29.6952)
  line L9 (-136.8552, -29.6952) -> (-136.7565, -29.9764)
  curve K4 (-111, -25) -> (-136.7565, -29.9764)
  point P15 (-136.7565, -29.9764)
  point P16 (-136.7565, -29.9764)
  point P20 (-111, -25)
  coincident P15 P16
  coincident L7 P20
extrude "Extrude38" new body sketch "Sketch41" profile of L1 K2 K3 L7 L8 L9 K4 against normal blind 10
sketch "Sketch42" plane through (0, 0, -29.6952) normal (0, 0, -1) x axis (1, 0, 0)
  line L1 (-19.9973, -141.5245) -> (-19.9973, -136.8552)
  line L2 (-9.9973, -141.5245) -> (-19.9973, -141.5245)
  line L3 (-9.9973, -136.8552) -> (-9.9973, -141.5245)
  line L4 (-19.9973, -136.8552) -> (-9.9973, -136.8552)
  curve K1 (-14.9977, -136.7565) -> (-19.9884, -143.7427)
extrude "Extrude39" new body sketch "Sketch42" profile of L1 L2 L4 K1 along normal blind 0.281
combine "Combine34"
extrude "Extrude40" add of existing geometry blind 0.1
sketch "Sketch43" plane through (0, 0, -29.6952) normal (0, 0, -1) x axis (1, 0, 0)
  line L1 (19.9977, -141.5245) -> (19.9977, -144.3129)
  line L2 (-19.9973, -141.5245) -> (19.9977, -141.5245)
  line L3 (-19.9973, -144.3129) -> (-19.9973, -141.5245)
  line L4 (19.9977, -144.3129) -> (-19.9973, -144.3129)
  curve K1 (-14.9977, -136.7565) -> (-19.9884, -143.7427)
  line L5 (-19.9973, -141.5245) -> (-19.9973, -144.3129)
  line L6 (-19.9973, -141.5245) -> (19.9977, -141.5245)
  line L7 (-19.9973, -143.8395) -> (-19.9884, -143.7427)
  point P6 (-19.9884, -143.7427)
  point P11 (-19.9884, -143.7427)
  point P12 (-19.9973, -143.8395)
  coincident P6 P11
  coincident L5 P12
extrude "Extrude41" new body sketch "Sketch43" profile of L2 L3 K1 L5 L6 L7 along normal blind 0.281
mirror "Mirror14" mirrorStitchTolerance 0.1
move_face "MoveFace37"
move_face "MoveFace38"
combine "Combine35"
fillet "Fillet48" radius 3
fillet "Fillet49" radius 1
chamfer "Chamfer9" distance 0.45
remove_body "RemoveBody5"
mirror "Mirror15" mirrorStitchTolerance 0.1
remove_body "RemoveBody6"
chamfer "Chamfer10" distance 0.45
combine "Combine36"
delete_face "DeleteFace36"
chamfer "Chamfer11" distance 2
fillet "Fillet50" radius 0.5
move_face "MoveFace39"
combine "Combine37"
sketch "Sketch44" plane through (0, 144.3129, 0) normal (0, 1, 0) x axis (-1, 0, 0)
  line L1 (-19.5477, -29.6952) -> (-19.9977, -29.2452)
  line L2 (19.5473, -29.6952) -> (-19.5477, -29.6952)
  line L3 (19.9973, -29.2452) -> (19.5473, -29.6952)
  line L4 (19.9973, 10) -> (19.9973, -29.2452)
  line L5 (-19.9977, 10) -> (19.9973, 10)
  line L6 (-19.9977, -29.2452) -> (-19.9977, 10)
  arc A1 centre (-0.116, -0.2904) radius 6.7256 clockwise from (-4.9991, 4.3345) to (6.222, 1.9596)
  arc A2 centre (-0.116, -0.2904) radius 6.7256 clockwise from (6.222, 1.9596) to (-6.4544, 1.9588)
  circle C1 centre (-0.116, -0.2904) radius 6.7256
  concentric A1 C1
extrude "Extrude42" cut sketch "Sketch44" profile of A1 A2 C1 against normal blind 245
delete_face "DeleteFace37"
move_face "MoveFace40"
move "Move16" RotateAngle -30
move_face "MoveFace41" RotateAngle 30
split "Split16"
fillet "Fillet51" radius 2
move_face "MoveFace42"
move_face "MoveFace43"
move_face "MoveFace44" RotateAngle 2.3
move "Move17" RotateAngle 30
combine "Combine38"
offset_faces "OffsetFaces2" distance -0.5
offset_faces "OffsetFaces3" distance -0.5
offset_faces "OffsetFaces4" distance -0.5
fillet "Fillet52" radius 1.5
combine "Combine39"
move_face "MoveFace45"
move_face "MoveFace46" RotateAngle 1.7
move "Move18" RotateAngle -30
move_face "MoveFace47"
fillet "Fillet53" radius 0.5
move_face "MoveFace48"
sketch "Sketch45" plane through (0, 19.0955, 0) normal (0, -1, 0) x axis (1, 0, 0)
  line L1 (17.9977, -3.324) -> (6.1186, -3.324)
  line L2 (17.9977, -3.324) -> (19.9977, 0.985)
  line L3 (19.9977, 10) -> (19.9977, 0.985)
  line L4 (-19.9973, 10) -> (19.9977, 10)
  line L5 (-19.9973, 0.985) -> (-19.9973, 10)
  line L6 (-19.9973, 0.985) -> (-17.9973, -3.324)
  line L7 (-5.8865, -3.324) -> (-17.9973, -3.324)
  arc A1 centre (0.116, -0.2904) radius 6.7256 clockwise from (-5.8865, -3.324) to (6.1186, -3.324)
  circle C1 centre (0.116, -0.2904) radius 8.4213
  concentric A1 C1
split "Split17"
remove_body "RemoveBody7"
move "Move1"
move_face "MoveFace1" TranslateX 0 TranslateY -17 TranslateZ 0
move_face "MoveFace2" TranslateX 0 TranslateY -17 TranslateZ 0
delete_face "DeleteFace38"
move_face "MoveFace49" TranslateX 0 TranslateY 0 TranslateZ 20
